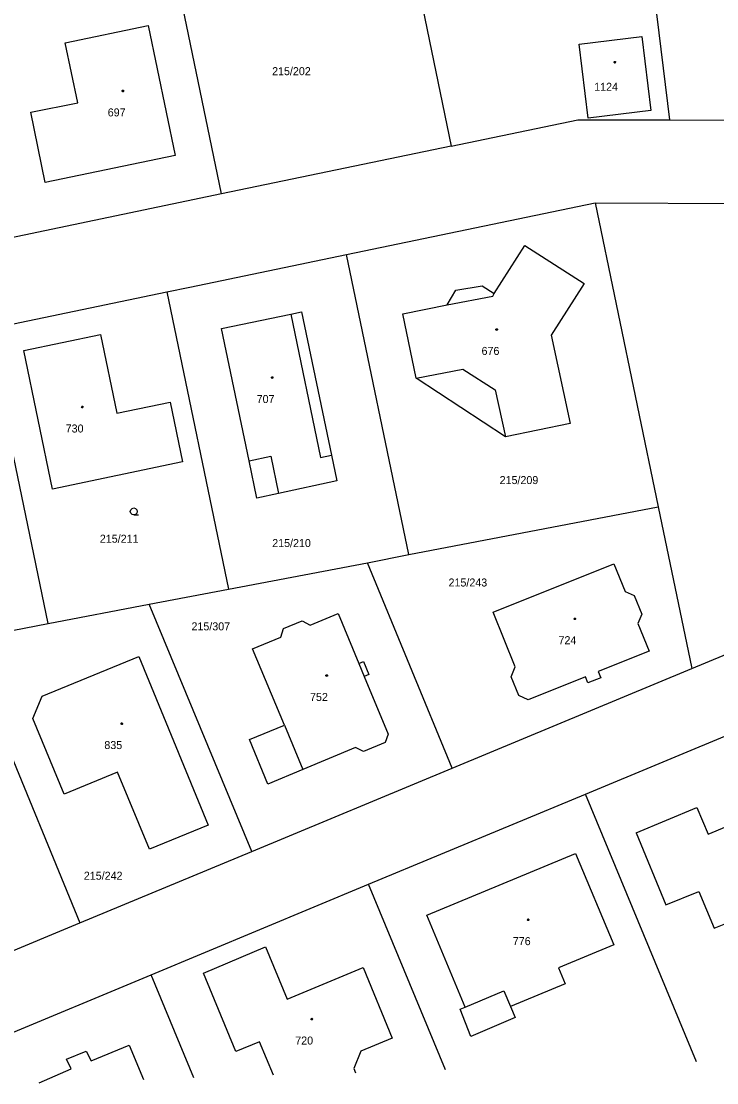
# Model space of a CAD drawing. Extents: x -757994 to -755874, y -1047691 to -1046119.
# Drawn here: x -757659.5 to -757585.5, y -1047690.6 to -1047577.8 of the extents above; entities that cross this region are included whole.
import ezdxf

# ---------------------------------------------------------------- set-up
doc = ezdxf.new("R2010")
doc.units = 0
doc.layers.add('katastrální mapa', color=7, linetype='Continuous')

msp = doc.modelspace()

# ---------------------------------------------------------------- linework, layer by layer
at = {"layer": 'katastrální mapa'}
for p, q in [((-757594.92, -1047552.84), (-757590.55, -1047588.32)), ((-757620.85, -1047556.95), (-757613.75, -1047591.1)), ((-757638.16, -1047596.18), (-757645.26, -1047561.99)), ((-757654.77, -1047580.11), (-757645.96, -1047578.3)), ((-757645.96, -1047578.3), (-757643.1, -1047592.08)), ((-757600.16, -1047580.27), (-757593.5, -1047579.46)), ((-757593.5, -1047579.46), (-757592.55, -1047587.31)), ((-757653.45, -1047586.49), (-757654.77, -1047580.11)), ((-757599.21, -1047588.12), (-757600.16, -1047580.27)), ((-757658.45, -1047587.5), (-757653.45, -1047586.49)), ((-757656.9, -1047594.97), (-757658.45, -1047587.5)), ((-757592.55, -1047587.31), (-757599.21, -1047588.12)), ((-757613.75, -1047591.1), (-757600.3, -1047588.3)), ((-757600.3, -1047588.3), (-757590.55, -1047588.32)), ((-757590.55, -1047588.32), (-757565.55, -1047588.37)), ((-757613.75, -1047591.1), (-757615.64, -1047591.49)), ((-757643.1, -1047592.08), (-757656.9, -1047594.97)), ((-757615.64, -1047591.49), (-757638.16, -1047596.18)), ((-757638.16, -1047596.18), (-757660.68, -1047600.86)), ((-757624.9, -1047602.61), (-757598.47, -1047597.11)), ((-757598.47, -1047597.11), (-757561.63, -1047597.28)), ((-757598.47, -1047597.11), (-757591.75, -1047629.42)), ((-757641.55, -1047606.08), (-757624.9, -1047602.61)), ((-757618.27, -1047634.49), (-757624.9, -1047602.61)), ((-757609.18, -1047606.76), (-757605.92, -1047601.66)), ((-757605.92, -1047601.66), (-757599.63, -1047605.68)), ((-757613.28, -1047606.41), (-757610.48, -1047605.93)), ((-757610.48, -1047605.93), (-757609.18, -1047606.76)), ((-757599.63, -1047605.68), (-757603.13, -1047611.17)), ((-757663.08, -1047610.56), (-757643.99, -1047606.59)), ((-757643.99, -1047606.59), (-757641.55, -1047606.08)), ((-757643.99, -1047606.59), (-757637.42, -1047638.15)), ((-757614.19, -1047607.97), (-757613.28, -1047606.41)), ((-757614.19, -1047607.97), (-757609.34, -1047607.02)), ((-757609.34, -1047607.02), (-757609.18, -1047606.76)), ((-757618.9, -1047608.9), (-757614.19, -1047607.97)), ((-757638.17, -1047610.48), (-757630.8, -1047608.95)), ((-757630.8, -1047608.95), (-757629.66, -1047608.71)), ((-757630.8, -1047608.95), (-757627.63, -1047624.17)), ((-757629.66, -1047608.71), (-757626.47, -1047623.93)), ((-757617.48, -1047615.74), (-757618.9, -1047608.9)), ((-757635.24, -1047624.53), (-757638.17, -1047610.48)), ((-757656.58, -1047641.82), (-757663.08, -1047610.56)), ((-757659.19, -1047612.82), (-757651.04, -1047611.12)), ((-757651.04, -1047611.12), (-757649.3, -1047619.48)), ((-757603.13, -1047611.17), (-757601.11, -1047620.55)), ((-757656.12, -1047627.55), (-757659.19, -1047612.82)), ((-757617.48, -1047615.74), (-757612.52, -1047614.8)), ((-757612.52, -1047614.8), (-757609.09, -1047617)), ((-757608, -1047621.99), (-757617.48, -1047615.74)), ((-757609.09, -1047617), (-757608, -1047621.99)), ((-757649.3, -1047619.48), (-757643.62, -1047618.29)), ((-757643.62, -1047618.29), (-757642.3, -1047624.65)), ((-757601.11, -1047620.55), (-757608, -1047621.99)), ((-757635.24, -1047624.53), (-757632.92, -1047624.05)), ((-757632.92, -1047624.05), (-757632.1, -1047627.99)), ((-757627.63, -1047624.17), (-757626.47, -1047623.93)), ((-757626.47, -1047623.93), (-757625.9, -1047626.67)), ((-757642.3, -1047624.65), (-757656.12, -1047627.55)), ((-757634.42, -1047628.48), (-757635.24, -1047624.53)), ((-757625.9, -1047626.67), (-757632.1, -1047627.99)), ((-757632.1, -1047627.99), (-757634.42, -1047628.48)), ((-757618.27, -1047634.49), (-757591.75, -1047629.42)), ((-757591.75, -1047629.42), (-757588.18, -1047646.58)), ((-757622.64, -1047635.36), (-757618.27, -1047634.49)), ((-757637.42, -1047638.15), (-757622.64, -1047635.36)), ((-757613.65, -1047657.17), (-757622.64, -1047635.36)), ((-757609.28, -1047640.62), (-757596.46, -1047635.46)), ((-757596.46, -1047635.46), (-757595.27, -1047638.42)), ((-757588.18, -1047646.58), (-757562.8, -1047636.04)), ((-757645.86, -1047639.77), (-757637.42, -1047638.15)), ((-757595.27, -1047638.42), (-757594.3, -1047638.84)), ((-757656.58, -1047641.82), (-757645.86, -1047639.77)), ((-757634.95, -1047666.02), (-757645.86, -1047639.77)), ((-757594.3, -1047638.84), (-757593.51, -1047640.83)), ((-757628.76, -1047641.99), (-757625.78, -1047640.76)), ((-757625.78, -1047640.76), (-757623.58, -1047646.05)), ((-757606.95, -1047646.42), (-757609.28, -1047640.62)), ((-757593.51, -1047640.83), (-757593.91, -1047641.81)), ((-757661.74, -1047642.81), (-757656.58, -1047641.82)), ((-757631.58, -1047642.35), (-757629.61, -1047641.53)), ((-757629.61, -1047641.53), (-757628.76, -1047641.99)), ((-757593.91, -1047641.81), (-757592.73, -1047644.76)), ((-757631.86, -1047643.28), (-757631.58, -1047642.35)), ((-757665.59, -1047643.54), (-757653.23, -1047673.62)), ((-757634.86, -1047644.52), (-757631.86, -1047643.28)), ((-757657.22, -1047649.52), (-757646.97, -1047645.3)), ((-757646.97, -1047645.3), (-757639.59, -1047663.22)), ((-757631.49, -1047652.62), (-757634.86, -1047644.52)), ((-757592.73, -1047644.76), (-757598.12, -1047646.92)), ((-757623.58, -1047646.05), (-757623.06, -1047645.84)), ((-757623.58, -1047646.05), (-757623.01, -1047647.43)), ((-757623.06, -1047645.84), (-757622.5, -1047647.22)), ((-757613.65, -1047657.17), (-757588.18, -1047646.58)), ((-757607.39, -1047647.46), (-757606.95, -1047646.42)), ((-757622.5, -1047647.22), (-757623.01, -1047647.43)), ((-757623.01, -1047647.43), (-757620.46, -1047653.55)), ((-757606.58, -1047649.46), (-757607.39, -1047647.46)), ((-757599.48, -1047647.47), (-757605.58, -1047649.92)), ((-757599.22, -1047648.12), (-757599.48, -1047647.47)), ((-757597.84, -1047647.59), (-757599.22, -1047648.12)), ((-757598.12, -1047646.92), (-757597.84, -1047647.59)), ((-757658.23, -1047651.89), (-757657.22, -1047649.52)), ((-757605.58, -1047649.92), (-757606.58, -1047649.46)), ((-757599.47, -1047659.93), (-757576.38, -1047650.34)), ((-757654.88, -1047659.93), (-757658.23, -1047651.89)), ((-757635.21, -1047654.15), (-757631.49, -1047652.62)), ((-757631.49, -1047652.62), (-757629.54, -1047657.32)), ((-757633.25, -1047658.87), (-757635.21, -1047654.15)), ((-757620.78, -1047654.46), (-757623.07, -1047655.42)), ((-757620.46, -1047653.55), (-757620.78, -1047654.46)), ((-757623.94, -1047655), (-757629.54, -1047657.32)), ((-757623.07, -1047655.42), (-757623.94, -1047655)), ((-757649.21, -1047657.61), (-757654.88, -1047659.93)), ((-757645.81, -1047665.8), (-757649.21, -1047657.61)), ((-757634.95, -1047666.02), (-757613.65, -1047657.17)), ((-757629.54, -1047657.32), (-757633.25, -1047658.87)), ((-757622.56, -1047669.52), (-757599.47, -1047659.93)), ((-757587.68, -1047688.38), (-757599.47, -1047659.93)), ((-757586.45, -1047664.18), (-757576.33, -1047660)), ((-757594.11, -1047664.06), (-757587.64, -1047661.37)), ((-757587.64, -1047661.37), (-757586.45, -1047664.18)), ((-757639.59, -1047663.22), (-757645.81, -1047665.8)), ((-757594.11, -1047664.06), (-757590.96, -1047671.69)), ((-757653.23, -1047673.62), (-757634.95, -1047666.02)), ((-757616.33, -1047672.81), (-757600.54, -1047666.23)), ((-757600.54, -1047666.23), (-757596.47, -1047675.96)), ((-757645.64, -1047679.12), (-757622.56, -1047669.52)), ((-757614.38, -1047689.23), (-757622.56, -1047669.52)), ((-757590.96, -1047671.69), (-757587.45, -1047670.27)), ((-757587.45, -1047670.27), (-757585.8, -1047674.17)), ((-757669.02, -1047680.18), (-757653.23, -1047673.62)), ((-757612.27, -1047682.56), (-757616.33, -1047672.81)), ((-757585.8, -1047674.17), (-757582.68, -1047672.9)), ((-757640.08, -1047678.94), (-757633.51, -1047676.17)), ((-757633.51, -1047676.17), (-757631.18, -1047681.71)), ((-757596.47, -1047675.96), (-757602.35, -1047678.4)), ((-757667.85, -1047688.35), (-757645.64, -1047679.12)), ((-757641.1, -1047690.08), (-757645.64, -1047679.12)), ((-757636.66, -1047687.29), (-757640.08, -1047678.94)), ((-757631.18, -1047681.71), (-757623.13, -1047678.36)), ((-757623.13, -1047678.36), (-757620.03, -1047685.86)), ((-757602.35, -1047678.4), (-757601.65, -1047680.08)), ((-757601.65, -1047680.08), (-757607.46, -1047682.49)), ((-757612.27, -1047682.56), (-757608.15, -1047680.85)), ((-757608.15, -1047680.85), (-757607.46, -1047682.49)), ((-757612.81, -1047682.79), (-757612.27, -1047682.56)), ((-757607.46, -1047682.49), (-757606.97, -1047683.67)), ((-757611.66, -1047685.67), (-757612.81, -1047682.79)), ((-757606.97, -1047683.67), (-757611.66, -1047685.67)), ((-757620.03, -1047685.86), (-757623.37, -1047687.26)), ((-757652.03, -1047688.26), (-757647.98, -1047686.59)), ((-757647.98, -1047686.59), (-757646.46, -1047690.25)), ((-757634.14, -1047686.25), (-757636.66, -1047687.29)), ((-757632.66, -1047689.81), (-757634.14, -1047686.25)), ((-757654.65, -1047688.11), (-757652.56, -1047687.23)), ((-757654.15, -1047689.13), (-757654.65, -1047688.11)), ((-757652.56, -1047687.23), (-757652.03, -1047688.26)), ((-757623.37, -1047687.26), (-757624.12, -1047689.09)), ((-757657.56, -1047690.6), (-757654.15, -1047689.13)), ((-757624.12, -1047689.09), (-757623.94, -1047689.53))]:
    msp.add_line(p, q, dxfattribs=at)
for points in [[(-757596.36, -1047582.11), (-757596.31, -1047582.12), (-757596.28, -1047582.16), (-757596.27, -1047582.19), (-757596.28, -1047582.23), (-757596.33, -1047582.27), (-757596.36, -1047582.27), (-757596.41, -1047582.26), (-757596.44, -1047582.23), (-757596.45, -1047582.19), (-757596.44, -1047582.15), (-757596.4, -1047582.11)], [(-757648.65, -1047585.16), (-757648.6, -1047585.17), (-757648.58, -1047585.21), (-757648.57, -1047585.24), (-757648.58, -1047585.28), (-757648.61, -1047585.32), (-757648.65, -1047585.33), (-757648.7, -1047585.31), (-757648.73, -1047585.28), (-757648.74, -1047585.24), (-757648.73, -1047585.2), (-757648.69, -1047585.16)], [(-757608.92, -1047610.49), (-757608.87, -1047610.5), (-757608.85, -1047610.55), (-757608.84, -1047610.58), (-757608.85, -1047610.62), (-757608.89, -1047610.66), (-757608.92, -1047610.67), (-757608.97, -1047610.65), (-757609, -1047610.62), (-757609.01, -1047610.58), (-757609, -1047610.53), (-757608.96, -1047610.5)], [(-757632.77, -1047615.61), (-757632.72, -1047615.62), (-757632.7, -1047615.66), (-757632.69, -1047615.69), (-757632.7, -1047615.73), (-757632.74, -1047615.77), (-757632.77, -1047615.77), (-757632.82, -1047615.76), (-757632.85, -1047615.73), (-757632.85, -1047615.69), (-757632.85, -1047615.65), (-757632.8, -1047615.61)], [(-757652.96, -1047618.73), (-757652.91, -1047618.74), (-757652.89, -1047618.79), (-757652.88, -1047618.82), (-757652.89, -1047618.87), (-757652.93, -1047618.9), (-757652.96, -1047618.91), (-757653, -1047618.89), (-757653.03, -1047618.86), (-757653.04, -1047618.82), (-757653.03, -1047618.77), (-757652.99, -1047618.74)], [(-757600.62, -1047641.23), (-757600.57, -1047641.24), (-757600.54, -1047641.28), (-757600.53, -1047641.31), (-757600.54, -1047641.36), (-757600.59, -1047641.39), (-757600.62, -1047641.4), (-757600.67, -1047641.38), (-757600.7, -1047641.35), (-757600.71, -1047641.31), (-757600.7, -1047641.27), (-757600.66, -1047641.23)], [(-757626.99, -1047647.25), (-757626.94, -1047647.26), (-757626.92, -1047647.31), (-757626.91, -1047647.34), (-757626.92, -1047647.39), (-757626.96, -1047647.42), (-757626.99, -1047647.43), (-757627.03, -1047647.41), (-757627.07, -1047647.38), (-757627.08, -1047647.34), (-757627.07, -1047647.29), (-757627.02, -1047647.26)], [(-757648.77, -1047652.37), (-757648.72, -1047652.38), (-757648.7, -1047652.42), (-757648.69, -1047652.45), (-757648.7, -1047652.49), (-757648.74, -1047652.53), (-757648.77, -1047652.53), (-757648.82, -1047652.52), (-757648.85, -1047652.49), (-757648.85, -1047652.45), (-757648.85, -1047652.41), (-757648.8, -1047652.37)], [(-757605.58, -1047673.2), (-757605.53, -1047673.21), (-757605.5, -1047673.25), (-757605.49, -1047673.28), (-757605.5, -1047673.33), (-757605.54, -1047673.36), (-757605.58, -1047673.37), (-757605.62, -1047673.35), (-757605.66, -1047673.32), (-757605.67, -1047673.28), (-757605.66, -1047673.24), (-757605.61, -1047673.2)], [(-757628.57, -1047683.75), (-757628.52, -1047683.76), (-757628.49, -1047683.81), (-757628.48, -1047683.84), (-757628.49, -1047683.89), (-757628.53, -1047683.92), (-757628.57, -1047683.93), (-757628.61, -1047683.91), (-757628.65, -1047683.88), (-757628.66, -1047683.84), (-757628.65, -1047683.79), (-757628.6, -1047683.76)]]:
    msp.add_lwpolyline(points, close=True, dxfattribs=at)
msp.add_lwpolyline([(-757647.49, -1047630.27), (-757647.68, -1047630.22), (-757647.82, -1047630.09), (-757647.86, -1047629.9), (-757647.82, -1047629.72), (-757647.68, -1047629.58), (-757647.49, -1047629.53), (-757647.31, -1047629.58), (-757647.18, -1047629.72), (-757647.12, -1047629.91), (-757647.18, -1047630.1), (-757647.31, -1047630.23), (-757647.5, -1047630.28), (-757647, -1047630.28)], dxfattribs=at)

# ---------------------------------------------------------------- texts
for s, p in [('215/202', (-757632.79, -1047583.56)), ('1124', (-757598.56, -1047585.22)), ('697', (-757650.26, -1047587.94)), ('676', (-757610.53, -1047613.28)), ('707', (-757634.43, -1047618.39)), ('730', (-757654.73, -1047621.52)), ('215/209', (-757608.61, -1047627)), ('215/211', (-757651.1, -1047633.23)), ('215/210', (-757632.78, -1047633.69)), ('215/243', (-757614.04, -1047637.88)), ('215/307', (-757641.36, -1047642.54)), ('724', (-757602.35, -1047644.01)), ('752', (-757628.76, -1047650.04)), ('835', (-757650.62, -1047655.15)), ('215/242', (-757652.8, -1047669.03)), ('776', (-757607.21, -1047675.98)), ('720', (-757630.33, -1047686.54))]:
    msp.add_text(s, height=0.85, dxfattribs=at).set_placement(p)

doc.saveas('drawing.dxf')
